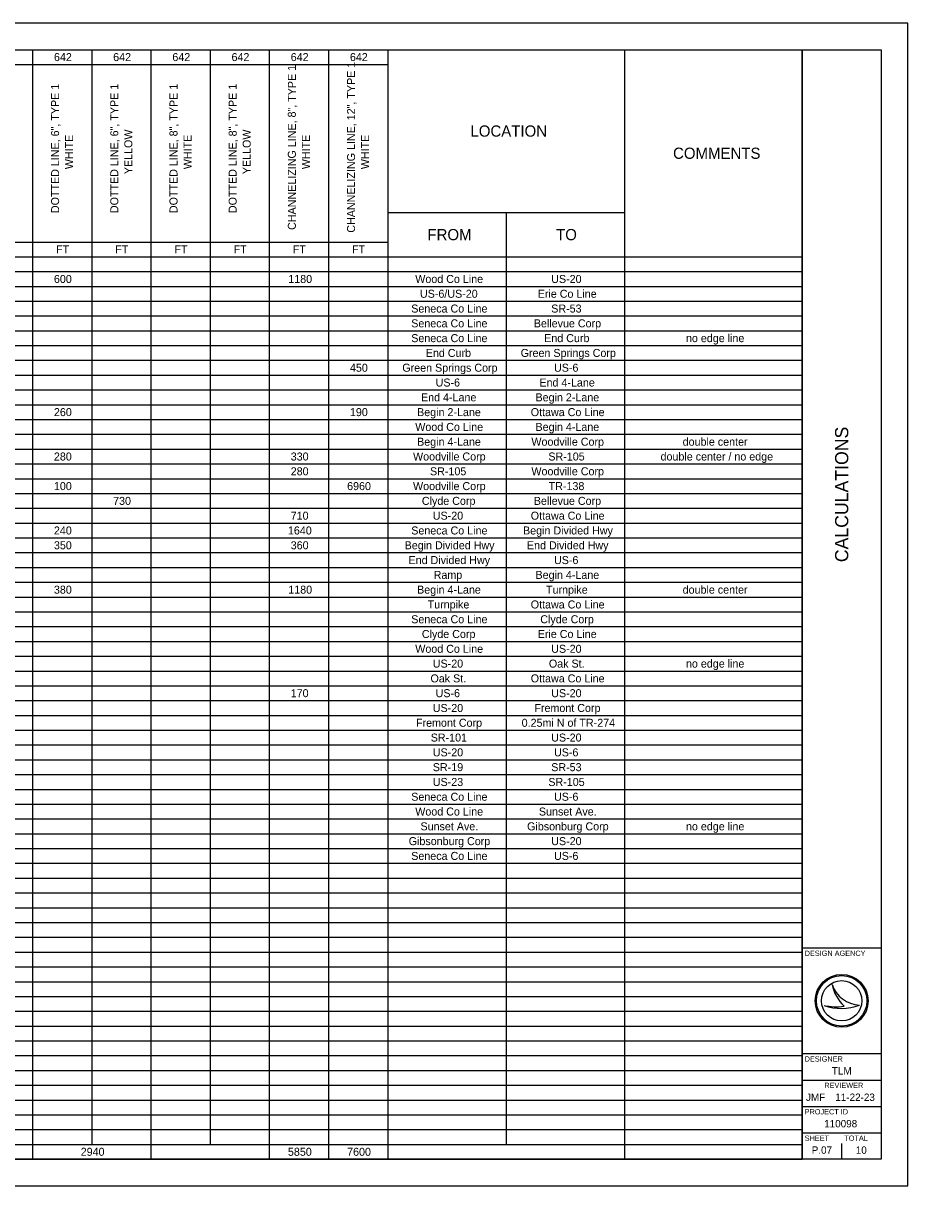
# Model space of a CAD drawing. Extents: x 0 to 34, y 0 to 22.
# Drawn here: x 17.27 to 34, y 0 to 22 of the extents above; entities that cross this region are included whole.
import ezdxf

# ---------------------------------------------------------------- set-up
doc = ezdxf.new("R2010")
doc.units = 0
for name, color, linetype in [('Default', 7, 'Continuous'), ('SH_Border', 7, 'Continuous'), ('SH_Cut_Line', 7, 'Continuous'), ('SH_Data', 7, 'Continuous')]:
    doc.layers.add(name, color=color, linetype=linetype)

msp = doc.modelspace()

# ---------------------------------------------------------------- linework, layer by layer
at = {"layer": 'Default'}
for p, q in [((1.5, 21.5), (32, 21.5)), ((17.442, 21.5), (17.442, 0.502)), ((18.562, 21.5), (18.562, 0.782)), ((19.681, 21.5), (19.681, 0.502)), ((20.801, 21.5), (20.801, 0.782)), ((21.921, 21.5), (21.921, 0.502)), ((23.041, 21.5), (23.041, 0.502)), ((24.161, 21.5), (24.161, 0.502)), ((28.64, 21.5), (28.64, 0.502)), ((32, 21.5), (32, 0.502)), ((8.483, 21.22), (24.161, 21.22)), ((24.161, 18.42), (28.64, 18.42)), ((26.401, 18.42), (26.401, 0.782)), ((8.483, 17.86), (24.161, 17.86)), ((1.5, 17.58), (32, 17.58)), ((1.5, 17.3), (32, 17.3)), ((2.505, 17.021), (32, 17.021)), ((2.505, 16.741), (32, 16.741)), ((2.505, 16.461), (32, 16.461)), ((2.505, 16.181), (32, 16.181)), ((2.505, 15.901), (32, 15.901)), ((2.505, 15.621), (32, 15.621)), ((2.505, 15.341), (32, 15.341)), ((2.505, 15.061), (32, 15.061)), ((2.505, 14.781), (32, 14.781)), ((2.505, 14.501), (32, 14.501)), ((2.505, 14.221), (32, 14.221)), ((2.505, 13.941), (32, 13.941)), ((2.505, 13.661), (32, 13.661)), ((2.505, 13.381), (32, 13.381)), ((2.505, 13.101), (32, 13.101)), ((2.505, 12.821), (32, 12.821)), ((2.505, 12.541), (32, 12.541)), ((2.505, 12.261), (32, 12.261)), ((2.505, 11.981), (32, 11.981)), ((2.505, 11.701), (32, 11.701)), ((2.505, 11.421), (32, 11.421)), ((2.505, 11.141), (32, 11.141)), ((2.505, 10.861), (32, 10.861)), ((2.505, 10.581), (32, 10.581)), ((2.505, 10.301), (32, 10.301)), ((2.505, 10.021), (32, 10.021)), ((2.505, 9.741), (32, 9.741)), ((2.505, 9.461), (32, 9.461)), ((2.505, 9.181), (32, 9.181)), ((2.505, 8.901), (32, 8.901)), ((2.505, 8.621), (32, 8.621)), ((2.505, 8.342), (32, 8.342)), ((2.505, 8.062), (32, 8.062)), ((2.505, 7.782), (32, 7.782)), ((2.505, 7.502), (32, 7.502)), ((2.505, 7.222), (32, 7.222)), ((2.505, 6.942), (32, 6.942)), ((2.505, 6.662), (32, 6.662)), ((2.505, 6.382), (32, 6.382)), ((1.5, 6.102), (32, 6.102)), ((1.5, 5.822), (32, 5.822)), ((1.5, 5.542), (32, 5.542)), ((1.5, 5.262), (32, 5.262)), ((1.5, 4.982), (32, 4.982)), ((1.5, 4.702), (32, 4.702)), ((1.5, 4.422), (32, 4.422)), ((1.5, 4.142), (32, 4.142)), ((1.5, 3.862), (32, 3.862)), ((1.5, 3.582), (32, 3.582)), ((1.5, 3.302), (32, 3.302)), ((1.5, 3.022), (32, 3.022)), ((1.5, 2.742), (32, 2.742)), ((1.5, 2.462), (32, 2.462)), ((1.5, 2.182), (32, 2.182)), ((1.5, 1.902), (32, 1.902)), ((1.5, 1.622), (32, 1.622)), ((1.5, 1.342), (32, 1.342)), ((1.5, 1.062), (32, 1.062)), ((1.5, 0.782), (32, 0.782)), ((1.5, 0.502), (32, 0.502))]:
    msp.add_line(p, q, dxfattribs=at)
at = {"layer": 'SH_Border'}
for p, q in [((32, 0.5), (32, 21.5)), ((32, 4.5), (33.5, 4.5)), ((32, 2.5), (33.5, 2.5)), ((32, 2), (33.5, 2)), ((32, 1.5), (33.5, 1.5)), ((32, 1), (33.5, 1))]:
    msp.add_line(p, q, dxfattribs=at)
msp.add_lwpolyline([(1.5, 21.5), (33.5, 21.5), (33.5, 0.5), (1.5, 0.5)], close=True, dxfattribs=at)
at = {"layer": 'SH_Cut_Line'}
msp.add_lwpolyline([(0, 0), (34, 0), (34, 22), (0, 22)], close=True, dxfattribs=at)
at = {"layer": 'SH_Data'}
for p, q in [((32.567, 3.81), (32.567, 3.81)), ((32.417, 3.41), (32.417, 3.41)), ((32.75, 3.5), (32.75, 3.5)), ((33.087, 3.419), (33.087, 3.419)), ((32.375, 0.675), (32.375, 0.675)), ((32.75, 0.5), (32.75, 0.8))]:
    msp.add_line(p, q, dxfattribs=at)
for radius in [0.5, 0.477, 0.477, 0.382]:
    msp.add_circle((32.75, 3.5), radius, dxfattribs=at)
for centre, radius, start, end in [((33.116, 3.998), 0.58, 198.9257, 198.9319), ((33.347, 3.97), 0.796, 191.6379, 191.6421), ((33.116, 3.998), 0.58, 198.9319, 267.1657), ((33.347, 3.97), 0.796, 191.6421, 226.0947), ((32.739, 4.37), 1.013, 251.4576, 290.0832), ((32.648, 4.654), 1.266, 259.4964, 259.4995), ((32.739, 4.37), 1.013, 251.4527, 251.4576), ((32.648, 4.654), 1.266, 259.4995, 276.6672)]:
    msp.add_arc(centre, radius, start, end, dxfattribs=at)

# ---------------------------------------------------------------- texts
at = {"layer": 'Default'}
for s, height, p in [('642', 0.1515, (17.848, 21.284)), ('642', 0.1515, (18.968, 21.284)), ('642', 0.1515, (20.088, 21.284)), ('642', 0.1515, (21.207, 21.284)), ('642', 0.1515, (22.327, 21.284)), ('642', 0.1515, (23.447, 21.284)), ('LOCATION', 0.2121, (25.727, 19.854)), ('COMMENTS', 0.2121, (29.56, 19.434)), ('FROM', 0.2121, (24.913, 17.894)), ('TO', 0.2121, (27.347, 17.894)), ('FT', 0.1515, (17.887, 17.645)), ('FT', 0.1515, (19.007, 17.645)), ('FT', 0.1515, (20.127, 17.645)), ('FT', 0.1515, (21.247, 17.645)), ('FT', 0.1515, (22.367, 17.645)), ('FT', 0.1515, (23.486, 17.645)), ('600', 0.1515, (17.847, 17.085)), ('1180', 0.1515, (22.281, 17.085)), ('Wood Co Line', 0.15151, (24.683, 17.085)), ('US-20', 0.1515, (27.255, 17.085)), ('US-6/US-20', 0.1515, (24.772, 16.805)), ('Erie Co Line', 0.15151, (27, 16.805)), ('Seneca Co Line', 0.15151, (24.607, 16.525)), ('SR-53', 0.1515, (27.255, 16.525)), ('Seneca Co Line', 0.15151, (24.607, 16.245)), ('Bellevue Corp', 0.15151, (26.926, 16.245)), ('Seneca Co Line', 0.15151, (24.607, 15.965)), ('End Curb', 0.1515, (27.122, 15.965)), ('no edge line', 0.15151, (29.805, 15.965)), ('End Curb', 0.1515, (24.882, 15.685)), ('Green Springs Corp', 0.15151, (26.677, 15.685)), ('450', 0.1515, (23.447, 15.405)), ('Green Springs Corp', 0.15151, (24.438, 15.405)), ('US-6', 0.1515, (27.308, 15.405)), ('US-6', 0.1515, (25.068, 15.125)), ('End 4-Lane', 0.1515, (27.032, 15.125)), ('End 4-Lane', 0.1515, (24.792, 14.845)), ('Begin 2-Lane', 0.15151, (26.958, 14.845)), ('260', 0.1515, (17.847, 14.565)), ('190', 0.1515, (23.447, 14.565)), ('Begin 2-Lane', 0.15151, (24.718, 14.565)), ('Ottawa Co Line', 0.15151, (26.868, 14.565)), ('Wood Co Line', 0.15151, (24.683, 14.285)), ('Begin 4-Lane', 0.15151, (26.958, 14.285)), ('Begin 4-Lane', 0.15151, (24.718, 14.005)), ('Woodville Corp', 0.15151, (26.88, 14.005)), ('double center', 0.15151, (29.742, 14.005)), ('280', 0.1515, (17.847, 13.725)), ('330', 0.1515, (22.327, 13.725)), ('Woodville Corp', 0.15151, (24.641, 13.725)), ('SR-105', 0.1515, (27.201, 13.725)), ('double center / no edge', 0.15151, (29.324, 13.725)), ('280', 0.1515, (22.327, 13.445)), ('SR-105', 0.1515, (24.962, 13.445)), ('Woodville Corp', 0.15151, (26.88, 13.445)), ('100', 0.1515, (17.847, 13.165)), ('6960', 0.1515, (23.394, 13.165)), ('Woodville Corp', 0.15151, (24.641, 13.165)), ('TR-138', 0.1515, (27.207, 13.165)), ('730', 0.1515, (18.967, 12.885)), ('Clyde Corp', 0.1515, (24.808, 12.885)), ('Bellevue Corp', 0.15151, (26.926, 12.885)), ('Ottawa Co Line', 0.15151, (26.868, 12.605)), ('710', 0.1515, (22.327, 12.605)), ('US-20', 0.1515, (25.015, 12.605)), ('240', 0.1515, (17.847, 12.325)), ('1640', 0.1515, (22.274, 12.325)), ('Seneca Co Line', 0.15151, (24.607, 12.325)), ('Begin Divided Hwy', 0.15151, (26.722, 12.325)), ('350', 0.1515, (17.847, 12.045)), ('360', 0.1515, (22.327, 12.045)), ('Begin Divided Hwy', 0.15151, (24.482, 12.045)), ('End Divided Hwy', 0.15151, (26.796, 12.045)), ('End Divided Hwy', 0.15151, (24.556, 11.765)), ('US-6', 0.1515, (27.308, 11.765)), ('Ramp', 0.1515, (25.031, 11.485)), ('Begin 4-Lane', 0.15151, (26.958, 11.485)), ('380', 0.1515, (17.847, 11.205)), ('1180', 0.1515, (22.281, 11.205)), ('Begin 4-Lane', 0.15151, (24.718, 11.205)), ('Turnpike', 0.1515, (27.157, 11.205)), ('double center', 0.15151, (29.742, 11.205)), ('Turnpike', 0.1515, (24.918, 10.925)), ('Ottawa Co Line', 0.15151, (26.868, 10.925)), ('Seneca Co Line', 0.15151, (24.607, 10.645)), ('Clyde Corp', 0.1515, (27.048, 10.645)), ('Clyde Corp', 0.1515, (24.808, 10.366)), ('Erie Co Line', 0.15151, (27, 10.366)), ('Wood Co Line', 0.15151, (24.683, 10.086)), ('US-20', 0.1515, (27.255, 10.086)), ('US-20', 0.1515, (25.015, 9.806)), ('Oak St.', 0.1515, (27.211, 9.806)), ('no edge line', 0.15151, (29.805, 9.806)), ('Oak St.', 0.1515, (24.971, 9.526)), ('Ottawa Co Line', 0.15151, (26.868, 9.526)), ('170', 0.1515, (22.327, 9.246)), ('US-6', 0.1515, (25.068, 9.246)), ('US-20', 0.1515, (27.255, 9.246)), ('US-20', 0.1515, (25.015, 8.966)), ('Fremont Corp', 0.15151, (26.937, 8.966)), ('Fremont Corp', 0.15151, (24.697, 8.686)), ('0.25mi N of TR-274', 0.15151, (26.696, 8.686)), ('SR-101', 0.1515, (24.975, 8.406)), ('US-20', 0.1515, (27.255, 8.406)), ('US-20', 0.1515, (25.015, 8.126)), ('US-6', 0.1515, (27.308, 8.126)), ('SR-19', 0.1515, (25.015, 7.846)), ('SR-53', 0.1515, (27.255, 7.846)), ('US-23', 0.1515, (25.015, 7.566)), ('SR-105', 0.1515, (27.201, 7.566)), ('Seneca Co Line', 0.15151, (24.607, 7.286)), ('US-6', 0.1515, (27.308, 7.286)), ('Wood Co Line', 0.15151, (24.683, 7.006)), ('Sunset Ave.', 0.15151, (27.022, 7.006)), ('Sunset Ave.', 0.15151, (24.782, 6.726)), ('Gibsonburg Corp', 0.15151, (26.799, 6.726)), ('no edge line', 0.15151, (29.805, 6.726)), ('Gibsonburg Corp', 0.15151, (24.559, 6.446)), ('US-20', 0.1515, (27.255, 6.446)), ('Seneca Co Line', 0.15151, (24.607, 6.166)), ('US-6', 0.1515, (27.308, 6.166)), ('2940', 0.1515, (18.354, 0.567)), ('5850', 0.1515, (22.274, 0.567)), ('7600', 0.1515, (23.394, 0.567))]:
    msp.add_text(s, height=height, dxfattribs=at).set_placement(p)
for s, height, p in [('CHANNELIZING LINE, 8", TYPE 1', 0.15151, (22.424, 18.089)), ('CHANNELIZING LINE, 12", TYPE 1', 0.15151, (23.544, 18.036)), ('DOTTED LINE, 6", TYPE 1', 0.15151, (17.945, 18.407)), ('DOTTED LINE, 6", TYPE 1', 0.15151, (19.065, 18.407)), ('DOTTED LINE, 8", TYPE 1', 0.15151, (20.185, 18.407)), ('DOTTED LINE, 8", TYPE 1', 0.15151, (21.304, 18.407)), ('WHITE', 0.1515, (18.21, 19.238)), ('YELLOW', 0.1515, (19.33, 19.144)), ('WHITE', 0.1515, (20.45, 19.238)), ('YELLOW', 0.1515, (21.57, 19.144)), ('WHITE', 0.1515, (22.689, 19.238)), ('WHITE', 0.1515, (23.809, 19.238))]:
    msp.add_text(s, height=height, rotation=90, dxfattribs=at).set_placement(p)
at = {"layer": 'SH_Data'}
msp.add_text('CALCULATIONS', height=0.25, rotation=90, dxfattribs=at).set_placement((32.875, 11.801))
for s, height, p in [('DESIGN AGENCY', 0.1, (32.05, 4.35)), ('DESIGNER', 0.1, (32.05, 2.35)), ('TLM', 0.14, (32.565, 2.105)), ('REVIEWER', 0.1, (32.422, 1.85)), ('JMF', 0.14, (32.075, 1.605)), ('11-22-23', 0.14, (32.629, 1.605)), ('PROJECT ID', 0.1, (32.05, 1.35)), ('110098', 0.14, (32.419, 1.105)), ('SHEET', 0.1, (32.05, 0.85)), ('TOTAL', 0.1, (32.8, 0.85)), ('P.07', 0.14, (32.183, 0.605)), ('10', 0.14, (33.017, 0.605))]:
    msp.add_text(s, height=height, dxfattribs=at).set_placement(p)

doc.saveas('drawing.dxf')
